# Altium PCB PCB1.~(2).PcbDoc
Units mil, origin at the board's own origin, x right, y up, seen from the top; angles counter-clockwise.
Board outline 6000 x 4000 mil, 2 copper layers (Top Layer, Bottom Layer); 1 components, 0 nets, 30 pads, 0 vias.
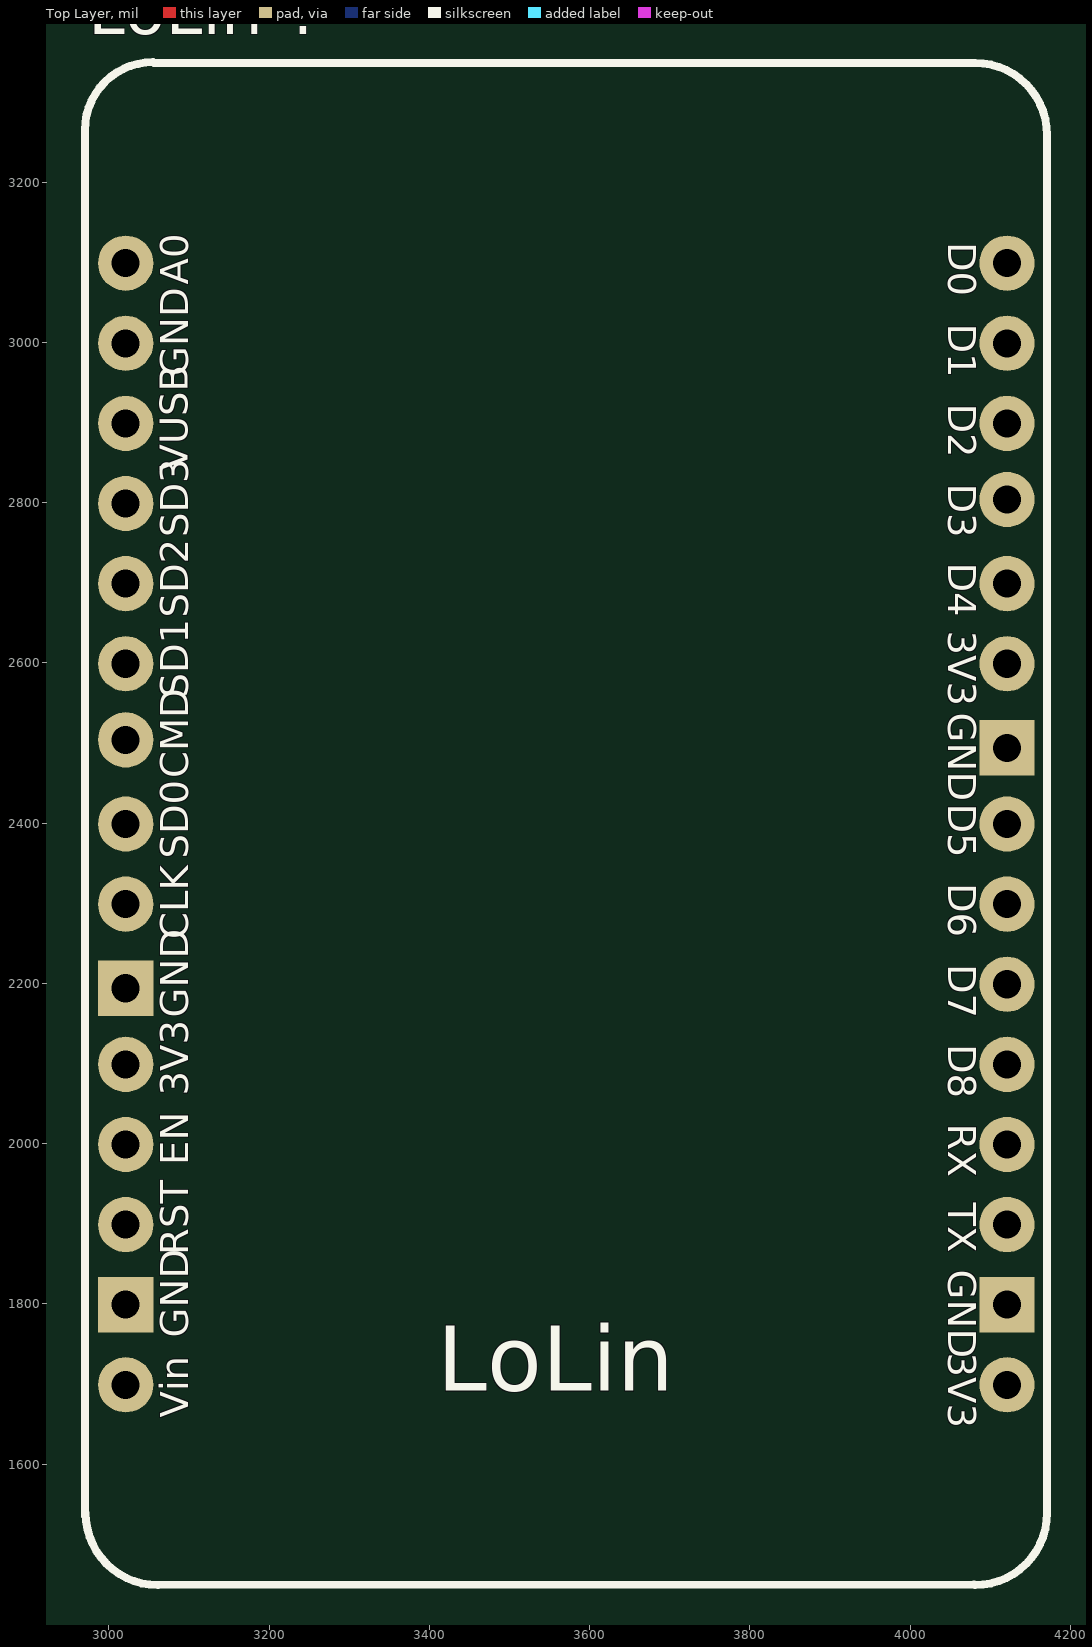
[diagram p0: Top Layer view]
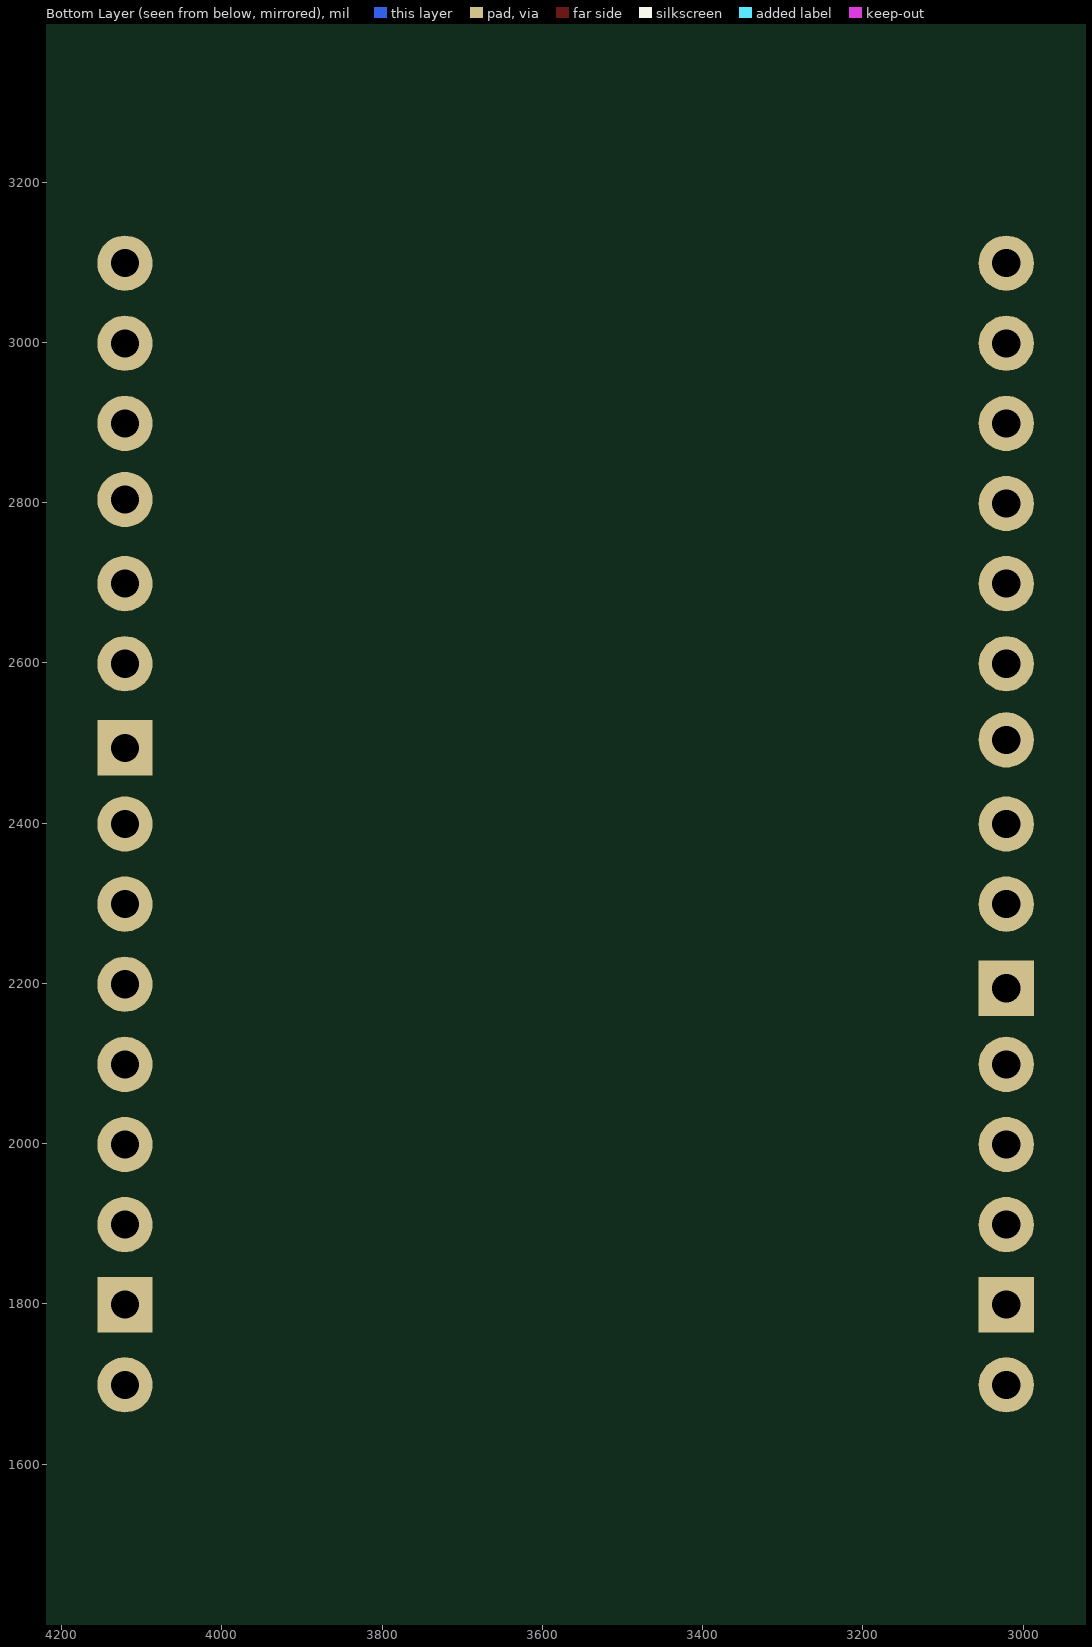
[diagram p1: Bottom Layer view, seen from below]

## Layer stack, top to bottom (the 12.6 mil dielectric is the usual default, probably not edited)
Top Solder: solder mask 0.4, Solder Resist, Dk 3.5
Top Layer: signal copper 1.4
Dielectric 1: dielectric 12.6, FR-4, Dk 4.8
Bottom Layer: signal copper 1.4
Bottom Solder: solder mask 0.4, Solder Resist, Dk 3.5

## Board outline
1000,1000 7000,1000 7000,5000 1000,5000

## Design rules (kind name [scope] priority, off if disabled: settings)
Clearance [All] p1: gap=10
PolygonConnect [All] p1: connectstyle=Relief reliefconductorwidth=10 reliefentries=4 polygonreliefangle="90 Angle" airgapwidth=10
RoutingVias [All] p1: holewidth=28 width=50 viastyle="Through Hole" minholewidth=28 minwidth=50 maxholewidth=28 maxwidth=50
SolderMaskExpansion [All] p1: expansion=4
Width [All] p1: maxlimit=10 minlimit=10 preferedwidth=10
30 further rules are at their usual default settings.

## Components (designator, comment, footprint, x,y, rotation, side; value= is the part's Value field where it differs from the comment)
LoLin-? "NodeMCU V1.0 ESP-12E_1" "LoLin NodeMcu V3" 3070,3345 r0 top

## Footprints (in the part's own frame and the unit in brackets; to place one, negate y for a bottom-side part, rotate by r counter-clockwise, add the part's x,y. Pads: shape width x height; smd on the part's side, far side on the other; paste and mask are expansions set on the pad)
"LoLin NodeMcu V3" [mil]
  round 69 hole 35: 3V3(-49,-1246) 3V3(1051,-1646) 3V3(1051,-746) A0(-49,-246) CLK(-49,-1046) CMD(-49,-841) D0(1051,-246) D1(1051,-346) D2(1051,-446) D3(1051,-541) D4(1051,-646) D5(1051,-946) D6(1051,-1046) D7(1051,-1146) D8(1051,-1246) EN(-49,-1346) GND(-49,-346) RST(-49,-1446) RX(1051,-1346) SD0(-49,-946) SD1(-49,-746) SD2(-49,-646) SD3(-49,-546) TX(1051,-1446) VIN(-49,-1646) VUSB(-49,-446)
  rect 69x69 hole 35: GND(-49,-1546) GND(-49,-1151) GND(1051,-1546) GND(1051,-851)
  silkscreen extent -100,-1896 1101,5

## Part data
LoLin-?: "LoLin NodeMCU V3"

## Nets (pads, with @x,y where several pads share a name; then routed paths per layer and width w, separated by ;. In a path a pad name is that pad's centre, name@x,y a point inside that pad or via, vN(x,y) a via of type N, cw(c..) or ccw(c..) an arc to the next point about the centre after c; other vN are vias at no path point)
pads on no net: LoLin-?.3V3 LoLin-?.A0 LoLin-?.CLK LoLin-?.CMD LoLin-?.D0 LoLin-?.D1 LoLin-?.D2 LoLin-?.D3 LoLin-?.D4 LoLin-?.D5 LoLin-?.D6 LoLin-?.D7 LoLin-?.D8 LoLin-?.EN LoLin-?.GND LoLin-?.RST LoLin-?.RX LoLin-?.SD0 LoLin-?.SD1 LoLin-?.SD2 LoLin-?.SD3 LoLin-?.TX LoLin-?.VIN LoLin-?.VUSB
